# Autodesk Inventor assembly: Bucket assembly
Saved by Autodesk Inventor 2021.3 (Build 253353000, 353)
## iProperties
Created: 2022-12
Part Number: Bucket assembly
Document SubType Name: Assembly
Designer: AdminForWorker
Title: Bucket assembly v2
Author: AdminForWorker
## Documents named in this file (3)
- c:\worker\convert-fusion-r07-cosv3\tmp\job-1\248\output\files\02726f4c-9815-42dc-95dc-176fb5068647\7f8063b0-6134-4457-85ab-1b0f45de5c97.iam
- c:\worker\convert-fusion-r07-cosv3\tmp\job-1\248\output\files\02726f4c-9815-42dc-95dc-176fb5068647\Lowe's Bucket Assembly(NON MODIFIED) v1.iam
- c:\worker\convert-fusion-r07-cosv3\tmp\job-1\248\output\files\02726f4c-9815-42dc-95dc-176fb5068647\Assembly v7.iam
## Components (2 placed, 2 different names)
1. Lowe's Bucket Assembly(NON MODIFIED) v1:1 [sub-assembly]
2. Assembly v7:1 [sub-assembly]
